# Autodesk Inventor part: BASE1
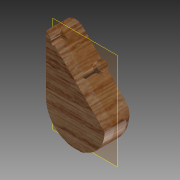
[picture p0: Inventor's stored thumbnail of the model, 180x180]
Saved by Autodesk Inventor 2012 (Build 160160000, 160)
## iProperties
Created: 2011-01
Part Number: BASE1
Document SubType Name: Modeling
Designer: Microsoft
Density: 1 g/cm^3
Material: Default
Author: Microsoft
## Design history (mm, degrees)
sketch "Sketch1"
  geometry: L1 (9.525, 0)-(9.525, 19.05); L2 (-9.525, 19.05)-(-9.525, 0); L3 (-9.525, 19.05)-(9.525, 0); A1 r 9.525 centre (0, 0) between (-9.525, 0) and (9.525, 0); A2 r 9.525 centre (0, 19.05) between (9.525, 19.05) and (-9.525, 19.05); 1 further point
  constraints: 6 end point, 4 point on circle, 3 tangent, 2 centre point, 1 coincident, 1 vertical alignment
  dimensions: "d3" = 9.525 radius of A2; "d4" = 9.525 radius of A1; "d5" = 19.05 distance of L1.start L1.end; "d6" = 19.05 distance of point (0, 0) A2.centre
extrude "Extrusion1" new body sketch "Sketch1" distance "d7" = 12.7; taper "d8" = 0 deg
sketch "Sketch2"
  geometry: L1 (13.47, 0)-(13.47, 12.7) reference; L2 (0, 0)-(26.941, 0) reference; C1 r 0.794 at (13.47, 6.35); 1 further point
  constraints: 1 centre point, 1 midpoint
  dimensions: "d31" = 1.5875 diameter of C1; "d32" = 6.35 distance from line of L2 C1.centre
extrude "Extrusion2" join sketch "Sketch2" distance "d10" = 6.35; taper "d11" = 0 deg
sketch "Sketch3"
  geometry: C1 r 1.587 at (0, -3.175); C2 r 0.794 at (0, -3.175) reference; 1 further point
  constraints: 1 centre point, 1 concentric
  dimensions: "d12" = 3.175 diameter of C1
extrude "Extrusion3" join sketch "Sketch3" distance "d13" = 1.5875; taper "d14" = 0 deg
workplane "Work Plane1"
sketch "Sketch5"
  geometry: L1 (-9.525, 19.05)-(-8.622, 19.953); L2 (9.525, 0)-(-9.525, 19.05) reference; C1 r 0.794 at (-7.28, 16.805); 1 further point
  constraints: 2 end point, 1 centre point, 1 perpendicular, 1 point on line
  dimensions: "d21" = 1.5875 diameter of C1; "d22" = 3.175 distance from line of L1 C1.centre
extrude "Extrusion4" cut sketch "Sketch5" distance "d23" = 3.175; taper "d24" = 0 deg
sketch "Sketch6"
  geometry: C1 r 1.588 at (-7.28, -16.805); A1 r 0.794 centre (-7.28, -16.805) between (-6.719, -16.244) and (-7.841, -17.366) reference; 1 further point
  constraints: 1 centre point, 1 coincident
  dimensions: "d25" = 3.175 diameter of C1
extrude "Extrusion5" cut sketch "Sketch6" distance "d26" = 1.5875; taper "d27" = 0 deg
fillet "Fillet1" dims "d30" = 2.54
sketch "Sketch8"
  geometry: L1 (-9.525, 19.05)-(9.525, 0) reference; L2 (-9.525, 0)-(-9.525, 19.05) reference; A1 r 9.525 centre (0, 0) between (-9.525, 0) and (9.525, 0) reference
extrude "Extrusion7" cut sketch "Sketch8" distance "d33" = 3.175; taper "d34" = 0 deg
sketch "Sketch9"
  geometry: L1 (7.841, -17.366)-(6.719, -16.244) reference; C1 r 1.588 at (7.28, -16.805); A1 r 0.794 centre (7.28, -16.805) between (6.719, -16.244) and (7.841, -17.366) reference; 1 further point
  constraints: 1 centre point, 1 coincident
  dimensions: "d37" = 3.175 diameter of C1
extrude "Extrusion8" cut sketch "Sketch9" distance "d35" = 0.79375; taper "d36" = 0 deg
workplane "Work Plane2"
workplane "Work Plane4"
workplane "Work Plane5"
sketch "Sketch14"
  geometry: L1 (1.588, -7.864)-(-1.587, -7.864); L2 (-1.587, -7.864)-(-1.587, -11.113); L3 (-1.587, -11.113)-(1.588, -11.113); L4 (1.588, -11.113)-(1.588, -7.864); L5 (0, -7.864)-(0, -11.113); 2 further points
  constraints: 10 end point, 2 midpoint, 2 parallel, 1 horizontal, 1 perpendicular
  dimensions: "d53" = 1.5875 distance from line of L4 point (0, 0); "d54" = 1.5875 distance from line of point (0, 0) L2; "d55" = 11.1125 distance from line of point (0, 0) L3
revolve "Revolution4" sketch "Sketch14" stored, may be unused: angle "d56" = 90 deg
workplane "Work Plane7"
sketch "Sketch16"
  geometry: L1 (-1.588, -11.113)-(1.587, -11.113) reference; L2 (0, -11.113)-(0, -9.525); C1 r 0.397 at (0, -10.319); A1 r 9.525 centre (0, 0) between (-9.525, 0) and (9.525, 0) reference; 1 further point
  constraints: 2 end point, 2 midpoint, 1 centre point, 1 perpendicular, 1 point on circle
  dimensions: "d63" = 0.79375 diameter of C1
extrude "Extrusion10" cut sketch "Sketch16" distance "d64" = 25.4; taper "d66" = 0 deg; dims "d65" = 12.7, "d67" = 0
body "Solid1"
other parameters: "d17" = -6.35, "d40" = 6.35, "d52" = -6.35, "d62" = -3.175
